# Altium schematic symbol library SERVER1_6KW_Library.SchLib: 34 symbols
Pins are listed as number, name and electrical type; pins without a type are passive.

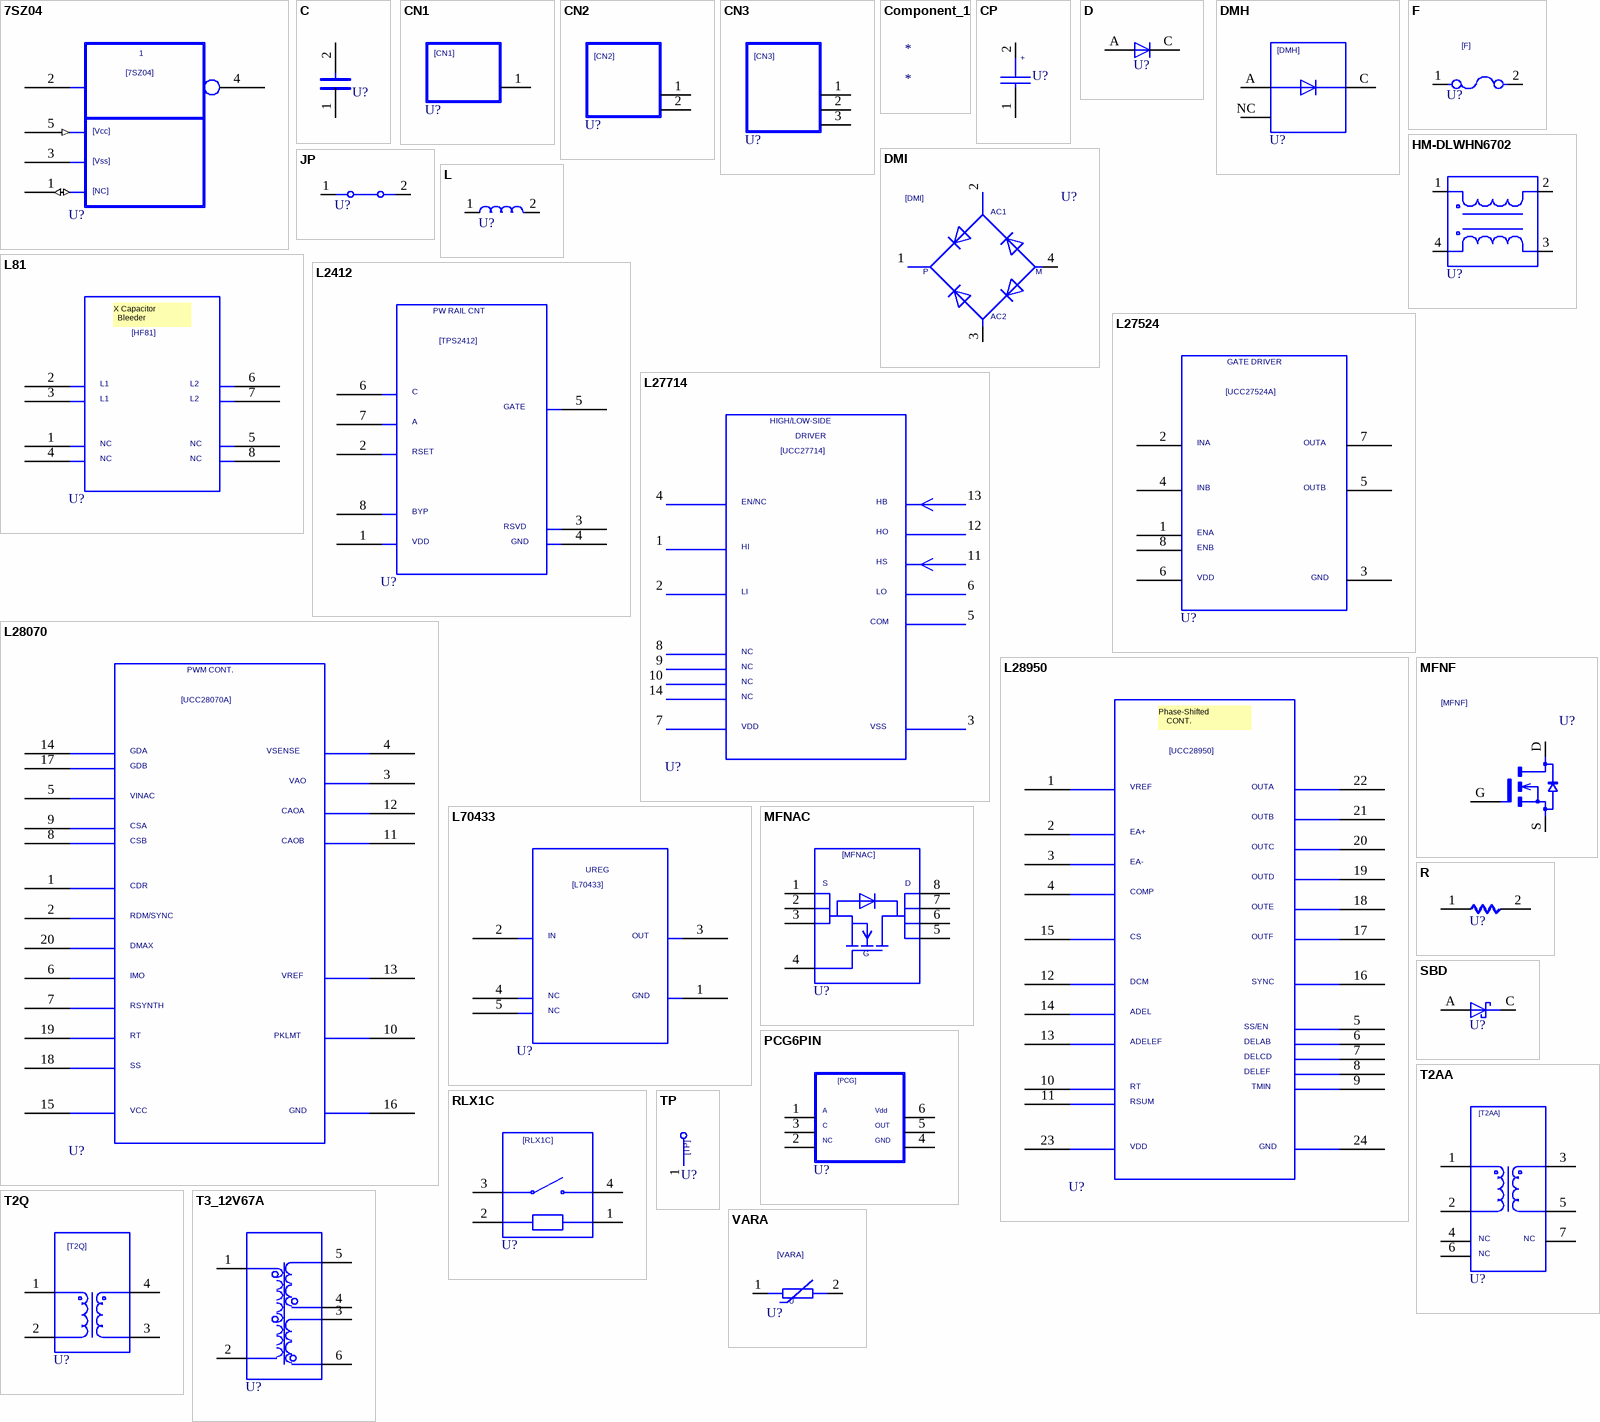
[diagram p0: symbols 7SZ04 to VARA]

## 7SZ04
designator U?  (value not drawn)
SAVEAREA0: -11095,0,51836,33020; TIME: 16:23:49; UPDATEUSER: s.maruyama; UPDATETIME: 20:33:11; SAVECOUNT: 7; OriginalSymbolOrigin: (7620,30480)
pins: 1 (io), 2, 3, 4, 5 (in)

## C
designator U?  (value not drawn)
OriginalSymbolOrigin: (2540,7620)
pins: 1, 2

## CN1
designator U?  (value not drawn)
OriginalSymbolOrigin: (2540,12700)
pins: 1

## CN2
designator U?  (value not drawn)
OriginalSymbolOrigin: (2540,15240)
pins: 1, 2

## CN3
designator U?  (value not drawn)
OriginalSymbolOrigin: (2540,17780)
pins: 1, 2, 3

## Component_1
designator *

## CP
designator U?  (value not drawn)
SAVEAREA0: -1450,-153,20294,13055; SAVECOUNT: 52; TIME: 15:02:55; UPDATEUSER: fukuda-y; UPDATETIME: 16:13:42; OriginalSymbolOrigin: (2540,10160)
pins: 1, 2

## D
designator U?  (value not drawn)
SAVEAREA0: -225,-91,12804,7836; SAVECOUNT: 3; TIME: 14:49:55; UPDATEUSER: 19870035; UPDATETIME: 14:20:16; OriginalSymbolOrigin: (5080,5080)
pins: A, C

## DMH
designator U?  (value not drawn)
SAVEAREA0: -4931,-287,27399,20979; TIME: 08:58:08; UPDATEUSER: kishi-s; UPDATETIME: 09:01:52; SAVECOUNT: 2; OriginalSymbolOrigin: (5080,17780)
pins: A, C, NC

## DMI
designator U?  (value not drawn)
SAVECOUNT: 7; SAVEAREA0: -7762,-358,32649,26224; TIME: 10:09:47; UPDATEUSER: fukuda-y; UPDATETIME: 17:30:39; OriginalSymbolOrigin: (0,25400)
pins: 1, 2, 3, 4

## F
designator U?  (value not drawn)
OriginalSymbolOrigin: (2540,5080)
pins: 1, 2

## HM-DLWHN6702
designator U?  (value not drawn)
DEVICENAME: DLW21HN670SQ2; SAVEAREA0: -21350,-26515,41553,39372; TIME: 11:39:40; UPDATEUSER: user1; UPDATETIME: 19:05:24; SAVECOUNT: 4; OriginalSymbolOrigin: (2540,12700)
pins: 1 (io), 2 (io), 3 (io), 4 (io)

## JP
designator U?  (value not drawn)
OriginalSymbolOrigin: (2540,5080)
pins: 1, 2

## L
designator U?  (value not drawn)
OriginalSymbolOrigin: (2540,5080)
pins: 1, 2

## L81
designator U?  (value not drawn)
SAVEAREA0: -12429,-3512,55842,41521; TIME: 18:31:00; UPDATEUSER: cae; UPDATETIME: 11:10:50; SAVECOUNT: 13; OriginalSymbolOrigin: (7620,35560)
pins: 1, 2, 3, 4, 5, 6, 7, 8

## L2412
designator U?  (value not drawn)
SAVEAREA0: -16399,-622,62276,51274; TIME: 11:49:52; UPDATEUSER: cae; UPDATETIME: 09:49:41; SAVECOUNT: 36; OriginalSymbolOrigin: (7620,48260)
pins: 1, 2, 3, 4, 5, 6, 7, 8

## L27524
designator U?  (value not drawn)
SAVEAREA0: -24347,-591,50370,48694; SAVECOUNT: 22; TIME: 15:02:55; UPDATEUSER: cae; UPDATETIME: 14:54:38; OriginalSymbolOrigin: (7620,45720)
pins: 1, 2, 3, 4, 5, 6, 7, 8

## L27714
designator U?  (value not drawn)
SAVEAREA0: -23586,-777,74646,64019; SAVECOUNT: 92; TIME: 14:04:55; UPDATEUSER: cae; UPDATETIME: 09:50:59; OriginalSymbolOrigin: (0,60960)
pins: 1, 2, 3, 4, 5, 6, 7, 8, 9, 10, 11, 12, 13, 14

## L28070
designator U?  (value not drawn)
SAVEAREA0: -12344,-1037,78634,87348; SAVECOUNT: 29; TIME: 15:02:55; UPDATEUSER: cae; UPDATETIME: 14:36:12; OriginalSymbolOrigin: (7620,83820)
pins: 1, 2, 3, 4, 5, 6, 7, 8, 9, 10, 11, 12, 13, 14, 15, 16, 17, 18, 19, 20

## L28950
designator U?  (value not drawn)
SAVEAREA0: -25263,1478,86635,87004; SAVECOUNT: 35; TIME: 15:02:55; UPDATEUSER: cae; UPDATETIME: 16:32:09; OriginalSymbolOrigin: (7620,83820)
pins: 1, 2, 3, 4, 5, 6, 7, 8, 9, 10, 11, 12, 13, 14, 15, 16, 17, 18, 19, 20, 21, 22, 23, 24

## L70433
designator U?  (value not drawn)
SAVEAREA0: -444,-3509,43701,41525; TIME: 18:31:00; UPDATEUSER: cae; UPDATETIME: 13:31:05; SAVECOUNT: 12; OriginalSymbolOrigin: (7620,35560)
pins: 1, 2, 3, 4, 5

## MFNAC
designator U?  (value not drawn)
TIME: 18:29:30; UPDATEUSER: 19990028; UPDATETIME: 14:45:16; SAVECOUNT: 26; SAVEAREA0: -10143,-336,37609,28718; OriginalSymbolOrigin: (5080,25400)
pins: 1, 2, 3, 4, 5, 6, 7, 8

## MFNF
designator U?  (value not drawn)
SAVECOUNT: 11; SAVEAREA0: -7027,-292,21786,15988; OriginalSymbolOrigin: (5080,12700)
pins: D, G, S

## PCG6PIN
designator U?  (value not drawn)
TIME: 11:12:30; UPDATEUSER: s.maruyama; UPDATETIME: 11:21:41; SAVECOUNT: 5; SAVEAREA0: -4197,-437,28946,21425; OriginalSymbolOrigin: (5080,17780)
pins: 1, 2, 3, 4, 5, 6

## R
designator U?  (value not drawn)
OriginalSymbolOrigin: (5080,5080)
pins: 1, 2

## RLX1C
designator U?  (value not drawn)
SAVECOUNT: 9; SAVEAREA0: -9347,-440,34039,23986; OriginalSymbolOrigin: (5080,20320)
pins: 1, 2, 3, 4

## SBD
designator U?  (value not drawn)
SAVEAREA0: -4630,-153,17114,13055; TIME: 14:49:55; UPDATEUSER: fukuda-y; UPDATETIME: 08:16:22; SAVECOUNT: 9; OriginalSymbolOrigin: (5080,5080)
pins: A, C

## T2AA
designator U?  (value not drawn)
TIME: 11:34:46; UPDATEUSER: cae; UPDATETIME: 17:58:40; SAVECOUNT: 10; SAVEAREA0: -20981,-344,43891,33349; OriginalSymbolOrigin: (5080,30480)
pins: 1, 2, 3, 4, 5 4, 6, 7

## T2Q
designator U?  (value not drawn)
OriginalSymbolOrigin: (5080,20320)
pins: 1, 2, 3, 4

## T3_12V67A
designator U?  (value not drawn)
SAVEAREA0: -17981,-312,40903,30271; TIME: 16:04:15; UPDATEUSER: cae; UPDATETIME: 11:22:50; SAVECOUNT: 21; OriginalSymbolOrigin: (5080,27432)
pins: 1 2, 2 1, 3 4, 4 5, 5 6, 6 3

## TP
designator U?  (value not drawn)
TIME: 16:12:21; UPDATEUSER: fukuda-y; UPDATETIME: 16:18:11; SAVECOUNT: 2; SAVEAREA0: -242,-92,12810,7836; OriginalSymbolOrigin: (0,7620)
pins: 1

## VARA
designator U?  (value not drawn)
SAVEAREA0: -9950,-8554,25168,13619; SAVECOUNT: 12; TIME: 09:56:50; UPDATEUSER: tomizawa-y; OriginalSymbolOrigin: (2540,5080)
pins: 1, 2

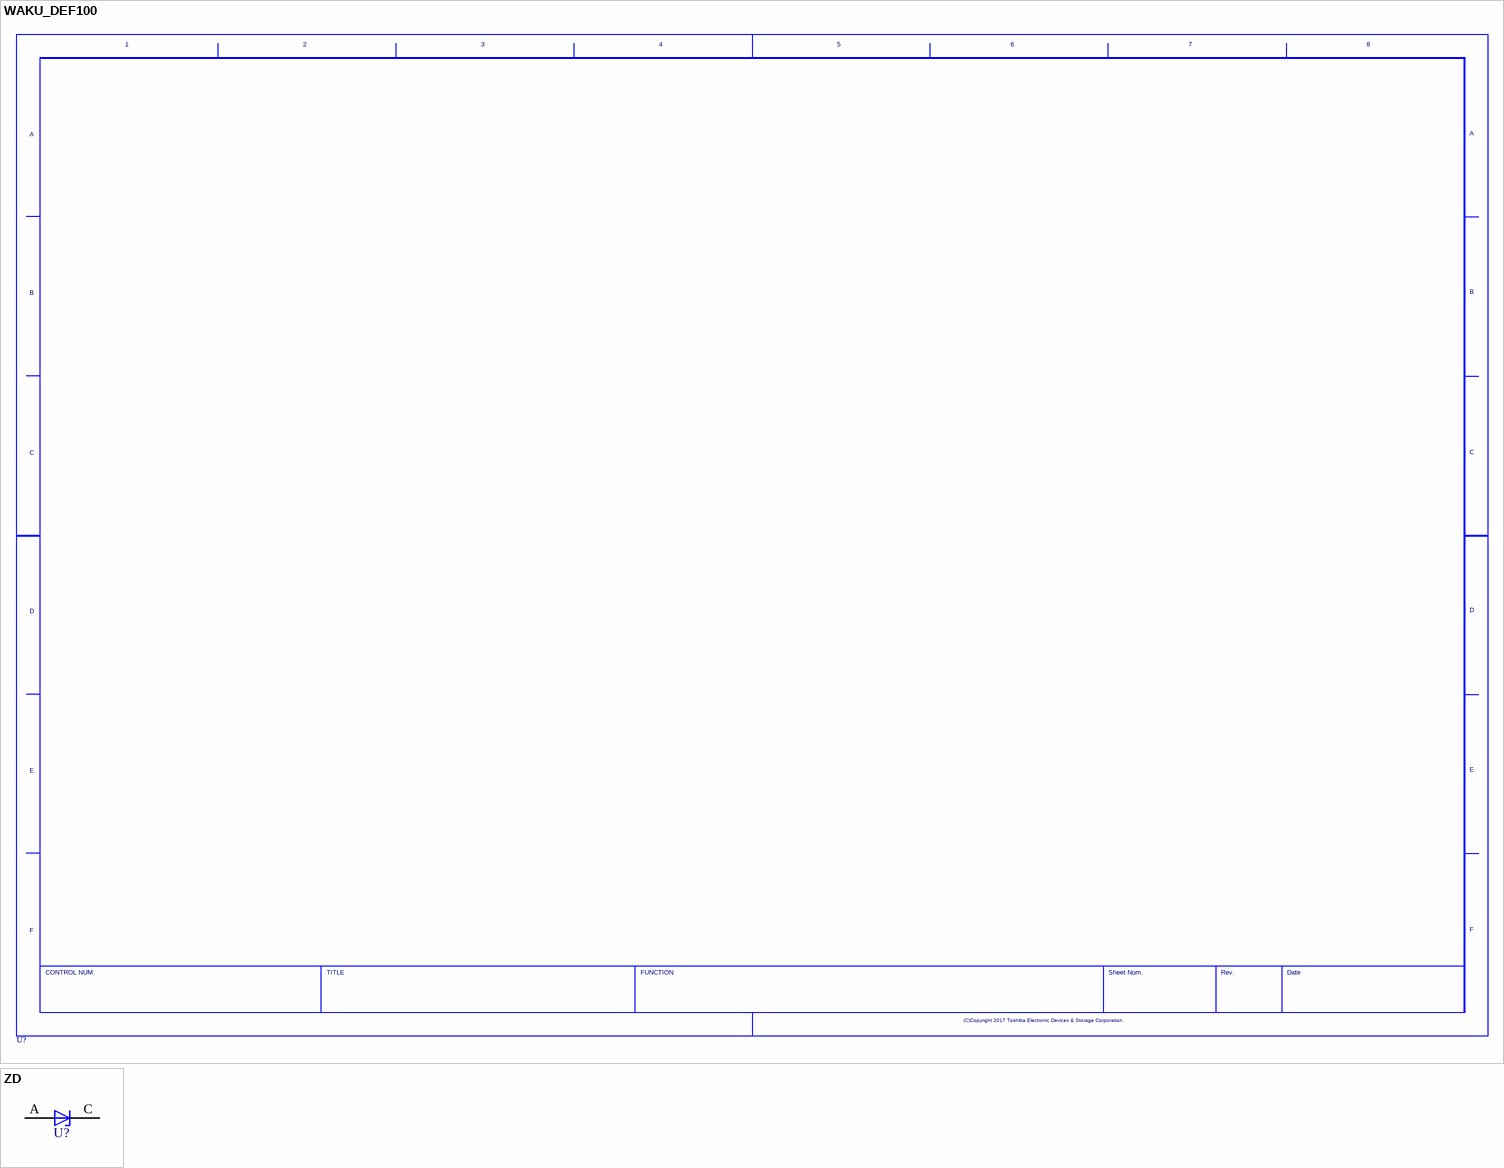
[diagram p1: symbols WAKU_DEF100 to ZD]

## WAKU_DEF100
designator U?  (value not drawn)
PLOTTIME: HH:MM; SAVEAREA0: -63393,-16950,474261,314592; TIME: 14:30:25; UPDATEUSER: cae; UPDATETIME: 18:29:18; SAVECOUNT: 3; OriginalSymbolOrigin: (10160,284480)

## ZD
designator U?  (value not drawn)
SAVEAREA0: -4630,-153,17114,13055; TIME: 14:49:55; UPDATEUSER: fukuda-y; UPDATETIME: 08:18:42; SAVECOUNT: 6; OriginalSymbolOrigin: (5080,5080)
pins: A, C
